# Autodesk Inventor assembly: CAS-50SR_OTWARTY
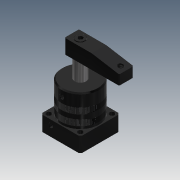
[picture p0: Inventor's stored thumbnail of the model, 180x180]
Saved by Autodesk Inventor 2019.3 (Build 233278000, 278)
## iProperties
Created: 2009-09
Part Number: CAS-50SR_OTWARTY
Material: Ogólny
Document SubType Name: Assembly
Designer: CADENGINEERING4
Sending System: PRO/ENGINEER BY PARAMETRIC TECHNOLOGY CORPORATION, 2007170
Preprocessor: PRO/ENGINEER BY PARAMETRIC TECHNOLOGY CORPORATION, 2007170
Title: CAS-50S_ASM
Author: Administrator
Revision Number: 1LAST_VERSION
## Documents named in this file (7)
- D:\Vault_2016\Projekty\STRONA\Pneumatic\Line ; Pipe connecct - type\cas-50s_asm\CAS-50SR_OTWARTY.iam
- D:\Vault_2016\Projekty\STRONA\Pneumatic\Line ; Pipe connecct - type\cas-50s_asm\CAS-50BT.ipt
- D:\Vault_2016\Projekty\STRONA\Pneumatic\Line ; Pipe connecct - type\cas-50s_asm\CAS-50SHSG.ipt
- D:\Vault_2016\Projekty\STRONA\Pneumatic\Line ; Pipe connecct - type\cas-50s_asm\CAS-50HG.ipt
- D:\Vault_2016\Projekty\STRONA\Pneumatic\Line ; Pipe connecct - type\cas-50s_asm\M4.ipt
- D:\Vault_2016\Projekty\STRONA\Pneumatic\Line ; Pipe connecct - type\cas-50s_asm\CAS-50SYB.ipt
- D:\Vault_2016\Projekty\STRONA\Pneumatic\Line ; Pipe connecct - type\cas-50s_asm\M10LC.ipt
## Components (9 placed, 9 different names)
1. CAS-50BT_0 — Kątowe:1
2. CAS-50SHSG_1 — Zestawiające:2
3. CAS-50HG_2
4. M4_3
5. M4_4
6. M4_5
7. M4_6
8. CAS-50SYB_7 — Zestawiające:1, Zestawiające:2, Kątowe:1
9. M10LC_8 — Zestawiające:1
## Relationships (3: Mate 2, Angle 1)
- Zestawiające:1 [Mate]: CAS-50SYB_7 ↔ M10LC_8
- Zestawiające:2 [Mate]: CAS-50SHSG_1 ↔ CAS-50SYB_7
- Kątowe:1 [Angle]: CAS-50BT_0 ↔ CAS-50SYB_7
